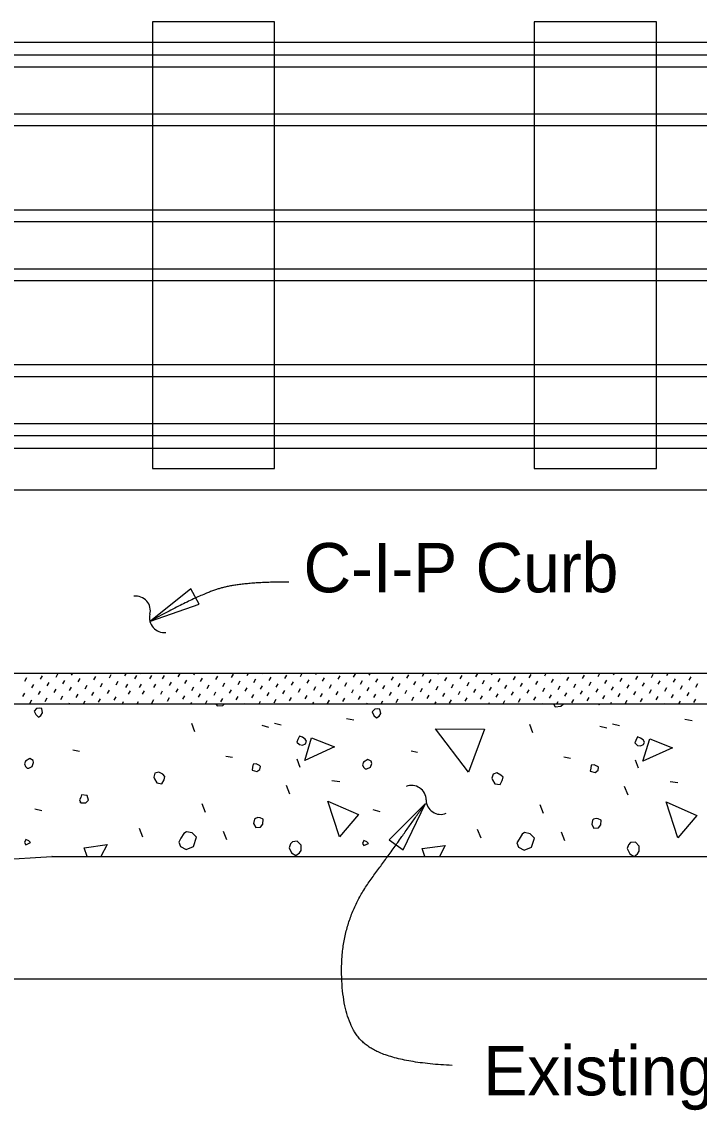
# Model space of a CAD drawing. Extents: x 1.5 to 68.7, y 0 to 31.1.
# Drawn here: x 31.375 to 34.147, y 9.197 to 13.648 of the extents above; entities that cross this region are included whole.
import ezdxf

# ---------------------------------------------------------------- set-up
doc = ezdxf.new("R2010")
doc.units = 0
for name, color, linetype in [('AdhocPoint_dp', 7, 'Continuous'), ('Patterning', 7, 'Continuous'), ('PlotBorder_dp', 7, 'Continuous'), ('SheetBorder_dp', 7, 'Continuous')]:
    doc.layers.add(name, color=color, linetype=linetype)

msp = doc.modelspace()

# ---------------------------------------------------------------- linework, layer by layer
at = {"layer": 'AdhocPoint_dp'}
for points in [[(31.9014, 11.1976), (32.1009, 11.2667), (32.067, 11.3286)], [(33.0264, 10.4517), (32.8772, 10.3022), (32.9348, 10.2614)]]:
    msp.add_lwpolyline(points, close=True, dxfattribs=at)
for centre, start, end in [((31.8414, 11.2396), 345.7563, 97.4835), ((31.9569, 11.2103), 165.7563, 277.4835), ((32.9696, 10.4655), 0.5042, 112.2314), ((33.0889, 10.4666), 180.5042, 292.2314)]:
    msp.add_arc(centre, 0.0596, start, end, dxfattribs=at)
for points in [[(32.467, 11.357), (32.2731, 11.357), (32.0952, 11.3038), (31.9014, 11.1976)], [(33.1354, 9.3803), (32.866, 9.3932), (32.6865, 9.5471), (32.68, 9.9706), (32.9173, 10.2978), (33.0264, 10.4518)]]:
    msp.add_open_spline(points, degree=2, dxfattribs=at)
at = {"layer": 'Patterning'}
for p, q in [((28.9195, 13.5645), (37.6978, 13.5645)), ((29.5771, 13.5123), (37.6978, 13.5123)), ((29.5783, 13.4641), (37.6978, 13.4641)), ((29.5831, 13.2713), (37.6978, 13.2713)), ((29.5842, 13.2231), (37.6978, 13.2231)), ((29.5807, 12.8791), (37.6978, 12.8791)), ((29.5795, 12.8309), (37.6978, 12.8309)), ((29.5747, 12.6381), (37.6978, 12.6381)), ((29.5735, 12.5899), (37.6978, 12.5899)), ((29.5842, 12.246), (37.6978, 12.246)), ((29.5831, 12.1978), (37.6978, 12.1978)), ((29.5783, 12.0049), (37.6978, 12.0049)), ((29.5771, 11.9567), (37.6978, 11.9567)), ((28.9195, 11.9044), (37.6978, 11.9044)), ((31.3878, 10.952), (31.3959, 10.966)), ((31.4513, 10.9601), (31.4594, 10.9741)), ((31.5148, 10.9682), (31.5229, 10.9822)), ((31.5425, 10.9405), (31.5506, 10.9545)), ((31.5783, 10.9763), (31.583, 10.9845)), ((31.606, 10.9486), (31.6141, 10.9626)), ((31.6418, 10.9844), (31.6418, 10.9845)), ((31.6695, 10.9567), (31.6776, 10.9707)), ((31.733, 10.9648), (31.7411, 10.9788)), ((31.7607, 10.9371), (31.7688, 10.9511)), ((31.7964, 10.9729), (31.8032, 10.9845)), ((31.8376, 10.9614), (31.8457, 10.9754)), ((31.8599, 10.981), (31.862, 10.9845)), ((31.8986, 10.9614), (31.9067, 10.9754)), ((31.9511, 10.9614), (31.9592, 10.9754)), ((32.0146, 10.9695), (32.0227, 10.9835)), ((32.0423, 10.9418), (32.0504, 10.9558)), ((32.0781, 10.9776), (32.0821, 10.9845)), ((32.1058, 10.9499), (32.1139, 10.9639)), ((32.1693, 10.958), (32.1774, 10.972)), ((32.2328, 10.9661), (32.2409, 10.9801)), ((32.2605, 10.9384), (32.2686, 10.9524)), ((32.2963, 10.9742), (32.3022, 10.9845)), ((32.324, 10.9465), (32.3321, 10.9605)), ((32.3598, 10.9823), (32.361, 10.9845)), ((32.3875, 10.9546), (32.3956, 10.9686)), ((32.451, 10.9627), (32.4591, 10.9767)), ((32.4787, 10.935), (32.4868, 10.949)), ((32.5145, 10.9708), (32.5224, 10.9845)), ((32.5422, 10.9431), (32.5503, 10.9571)), ((32.578, 10.9789), (32.5812, 10.9845)), ((32.6056, 10.9512), (32.6137, 10.9652)), ((32.6691, 10.9593), (32.6772, 10.9733)), ((32.7326, 10.9674), (32.7407, 10.9814)), ((32.7603, 10.9397), (32.7684, 10.9537)), ((32.7961, 10.9755), (32.8013, 10.9845)), ((32.8238, 10.9479), (32.8319, 10.9618)), ((32.8596, 10.9836), (32.8601, 10.9845)), ((32.8873, 10.956), (32.8954, 10.9699)), ((32.9508, 10.9641), (32.9589, 10.978)), ((32.9785, 10.9364), (32.9866, 10.9504)), ((33.0143, 10.9722), (33.0214, 10.9845)), ((33.042, 10.9445), (33.0501, 10.9585)), ((33.0778, 10.9803), (33.0802, 10.9845)), ((33.1055, 10.9526), (33.1136, 10.9666)), ((33.169, 10.9607), (33.1771, 10.9747)), ((33.2325, 10.9688), (33.2406, 10.9828)), ((33.2602, 10.9411), (33.2683, 10.9551)), ((33.296, 10.9769), (33.3004, 10.9845)), ((33.3237, 10.9492), (33.3318, 10.9632)), ((33.3871, 10.9573), (33.3952, 10.9713)), ((33.4506, 10.9654), (33.4587, 10.9794)), ((33.4783, 10.9377), (33.4864, 10.9517)), ((33.5141, 10.9735), (33.5205, 10.9845)), ((33.5418, 10.9458), (33.5499, 10.9598)), ((33.5776, 10.9816), (33.5793, 10.9845)), ((33.6053, 10.9539), (33.6134, 10.9679)), ((33.6688, 10.962), (33.6769, 10.976)), ((33.7323, 10.9701), (33.7404, 10.9841)), ((33.76, 10.9424), (33.7681, 10.9564)), ((33.7958, 10.9782), (33.7994, 10.9845)), ((33.8235, 10.9505), (33.8316, 10.9645)), ((33.887, 10.9586), (33.8951, 10.9726)), ((33.9505, 10.9667), (33.9586, 10.9807)), ((33.9782, 10.939), (33.9863, 10.953)), ((34.014, 10.9748), (34.0196, 10.9845)), ((34.0417, 10.9471), (34.0498, 10.9611)), ((34.0775, 10.9829), (34.0784, 10.9845)), ((34.1052, 10.9552), (34.1133, 10.9692)), ((31.4155, 10.9243), (31.4236, 10.9383)), ((31.4432, 10.8966), (31.4513, 10.9106)), ((31.479, 10.9324), (31.4871, 10.9464)), ((31.5067, 10.9047), (31.5148, 10.9187)), ((31.5702, 10.9128), (31.5783, 10.9268)), ((31.6337, 10.9209), (31.6418, 10.9349)), ((31.6614, 10.8932), (31.6695, 10.9072)), ((31.6972, 10.929), (31.7053, 10.943)), ((31.7249, 10.9013), (31.733, 10.9153)), ((31.8002, 10.9256), (31.8083, 10.9396)), ((31.8109, 10.8979), (31.8191, 10.9119)), ((31.856, 10.9256), (31.8641, 10.9396)), ((31.8681, 10.8979), (31.8762, 10.9119)), ((31.9153, 10.9256), (31.9234, 10.9396)), ((31.943, 10.8979), (31.9511, 10.9119)), ((31.9788, 10.9337), (31.9869, 10.9477)), ((32.0065, 10.906), (32.0146, 10.92)), ((32.07, 10.9141), (32.0781, 10.9281)), ((32.1335, 10.9222), (32.1416, 10.9362)), ((32.1612, 10.8945), (32.1693, 10.9085)), ((32.197, 10.9303), (32.2051, 10.9443)), ((32.2247, 10.9026), (32.2328, 10.9166)), ((32.2882, 10.9107), (32.2963, 10.9247)), ((32.3517, 10.9188), (32.3598, 10.9328)), ((32.3794, 10.8911), (32.3875, 10.9051)), ((32.4152, 10.9269), (32.4233, 10.9409)), ((32.4429, 10.8992), (32.451, 10.9132)), ((32.5064, 10.9073), (32.5145, 10.9213)), ((32.5698, 10.9154), (32.578, 10.9294)), ((32.6333, 10.9235), (32.6414, 10.9375)), ((32.661, 10.8958), (32.6691, 10.9098)), ((32.6968, 10.9316), (32.7049, 10.9456)), ((32.7245, 10.904), (32.7326, 10.9179)), ((32.788, 10.9121), (32.7961, 10.926)), ((32.8515, 10.9202), (32.8596, 10.9342)), ((32.8792, 10.8925), (32.8873, 10.9065)), ((32.915, 10.9283), (32.9231, 10.9423)), ((32.9427, 10.9006), (32.9508, 10.9146)), ((33.0062, 10.9087), (33.0143, 10.9227)), ((33.0697, 10.9168), (33.0778, 10.9308)), ((33.1332, 10.9249), (33.1413, 10.9389)), ((33.1609, 10.8972), (33.169, 10.9112)), ((33.1967, 10.933), (33.2048, 10.947)), ((33.2244, 10.9053), (33.2325, 10.9193)), ((33.2879, 10.9134), (33.296, 10.9274)), ((33.3513, 10.9215), (33.3595, 10.9355)), ((33.379, 10.8938), (33.3871, 10.9078)), ((33.4148, 10.9296), (33.4229, 10.9436)), ((33.4425, 10.9019), (33.4506, 10.9159)), ((33.506, 10.91), (33.5141, 10.924)), ((33.5695, 10.9181), (33.5776, 10.9321)), ((33.5972, 10.8904), (33.6053, 10.9044)), ((33.633, 10.9262), (33.6411, 10.9402)), ((33.6607, 10.8985), (33.6688, 10.9125)), ((33.6965, 10.9343), (33.7046, 10.9483)), ((33.7242, 10.9066), (33.7323, 10.9206)), ((33.7877, 10.9147), (33.7958, 10.9287)), ((33.8512, 10.9228), (33.8593, 10.9368)), ((33.8789, 10.8951), (33.887, 10.9091)), ((33.9147, 10.9309), (33.9228, 10.9449)), ((33.9424, 10.9032), (33.9505, 10.9172)), ((34.0059, 10.9113), (34.014, 10.9253)), ((34.0694, 10.9194), (34.0775, 10.9334)), ((34.0971, 10.8917), (34.1052, 10.9057)), ((34.1328, 10.9275), (34.141, 10.9415)), ((31.3797, 10.8885), (31.3878, 10.9025)), ((31.4074, 10.8608), (31.4155, 10.8748)), ((31.4709, 10.8689), (31.479, 10.8829)), ((31.5344, 10.877), (31.5425, 10.891)), ((31.568, 10.8595), (31.5702, 10.8633)), ((31.5979, 10.8851), (31.606, 10.8991)), ((31.6268, 10.8595), (31.6337, 10.8714)), ((31.6891, 10.8655), (31.6972, 10.8795)), ((31.7526, 10.8736), (31.7607, 10.8876)), ((31.7865, 10.8595), (31.7914, 10.868)), ((31.7881, 10.8595), (31.7883, 10.8599)), ((31.8469, 10.8595), (31.8518, 10.868)), ((31.9072, 10.8621), (31.9153, 10.8761)), ((31.9707, 10.8702), (31.9788, 10.8842)), ((32.0342, 10.8783), (32.0423, 10.8923)), ((32.067, 10.8595), (32.07, 10.8646)), ((32.0977, 10.8864), (32.1058, 10.9004)), ((32.1258, 10.8595), (32.1335, 10.8727)), ((32.1889, 10.8668), (32.197, 10.8808)), ((32.2524, 10.8749), (32.2605, 10.8889)), ((32.2872, 10.8595), (32.2882, 10.8612)), ((32.3159, 10.883), (32.324, 10.897)), ((32.346, 10.8595), (32.3517, 10.8693)), ((32.4071, 10.8634), (32.4152, 10.8774)), ((32.4706, 10.8715), (32.4787, 10.8855)), ((32.5341, 10.8796), (32.5422, 10.8936)), ((32.5661, 10.8595), (32.5698, 10.8659)), ((32.5975, 10.8877), (32.6056, 10.9017)), ((32.6252, 10.8601), (32.6333, 10.874)), ((32.6887, 10.8682), (32.6968, 10.8821)), ((32.7522, 10.8763), (32.7603, 10.8903)), ((32.7862, 10.8595), (32.788, 10.8626)), ((32.8157, 10.8844), (32.8238, 10.8984)), ((32.845, 10.8595), (32.8515, 10.8707)), ((32.9069, 10.8648), (32.915, 10.8788)), ((32.9704, 10.8729), (32.9785, 10.8869)), ((33.0339, 10.881), (33.042, 10.895)), ((33.0652, 10.8595), (33.0697, 10.8673)), ((33.0974, 10.8891), (33.1055, 10.9031)), ((33.1251, 10.8614), (33.1332, 10.8754)), ((33.1886, 10.8695), (33.1967, 10.8835)), ((33.2521, 10.8776), (33.2602, 10.8916)), ((33.2853, 10.8595), (33.2879, 10.8639)), ((33.3156, 10.8857), (33.3237, 10.8997)), ((33.3441, 10.8595), (33.3513, 10.872)), ((33.4067, 10.8661), (33.4148, 10.8801)), ((33.4702, 10.8742), (33.4783, 10.8882)), ((33.5054, 10.8595), (33.506, 10.8605)), ((33.5337, 10.8823), (33.5418, 10.8963)), ((33.5642, 10.8595), (33.5695, 10.8686)), ((33.6249, 10.8627), (33.633, 10.8767)), ((33.6884, 10.8708), (33.6965, 10.8848)), ((33.7519, 10.8789), (33.76, 10.8929)), ((33.7844, 10.8595), (33.7877, 10.8652)), ((33.8154, 10.887), (33.8235, 10.901)), ((33.8432, 10.8595), (33.8512, 10.8733)), ((33.9066, 10.8674), (33.9147, 10.8814)), ((33.9701, 10.8755), (33.9782, 10.8895)), ((34.0045, 10.8595), (34.0059, 10.8618)), ((34.0336, 10.8836), (34.0417, 10.8976)), ((34.0633, 10.8595), (34.0694, 10.8699)), ((34.1247, 10.864), (34.1328, 10.878)), ((32.0825, 10.7446), (32.0701, 10.7782)), ((32.3565, 10.7711), (32.3848, 10.764)), ((32.4082, 10.7804), (32.4365, 10.7733)), ((32.7038, 10.7994), (32.7339, 10.7941)), ((33.4657, 10.741), (33.4534, 10.7746)), ((33.7915, 10.7768), (33.8197, 10.7698)), ((34.0871, 10.7958), (34.1172, 10.7905)), ((33.7397, 10.7676), (33.768, 10.7605)), ((31.584, 10.6703), (31.6105, 10.665)), ((32.2097, 10.6456), (32.2363, 10.6403)), ((32.9672, 10.6668), (32.9937, 10.6615)), ((33.593, 10.6421), (33.6195, 10.6368)), ((32.5142, 10.5992), (32.5019, 10.6328)), ((33.8975, 10.5957), (33.8851, 10.6292)), ((32.4718, 10.4896), (32.4577, 10.5249)), ((32.6437, 10.5448), (32.6755, 10.5413)), ((33.8551, 10.486), (33.8409, 10.5214)), ((34.027, 10.5413), (34.0588, 10.5378)), ((31.4284, 10.4299), (31.4567, 10.4229)), ((32.1267, 10.414), (32.1125, 10.4494)), ((32.8117, 10.4264), (32.84, 10.4193)), ((33.5099, 10.4105), (33.4958, 10.4458)), ((31.8703, 10.3132), (31.8562, 10.3486)), ((32.2137, 10.3022), (32.1996, 10.3376)), ((33.2536, 10.3097), (33.2395, 10.3451)), ((33.597, 10.2987), (33.5829, 10.334))]:
    msp.add_line(p, q, dxfattribs=at)
for points in [[(31.9092, 11.8211), (32.4092, 11.8211), (32.4092, 13.6478), (31.9092, 13.6478)], [(33.4717, 11.8211), (33.9717, 11.8211), (33.9717, 13.6478), (33.4717, 13.6478)]]:
    msp.add_lwpolyline(points, close=True, dxfattribs=at)
for points in [[(32.169, 10.8594), (32.1744, 10.8507), (32.1974, 10.8524), (32.2044, 10.8594)], [(33.5501, 10.8594), (33.5577, 10.8471), (33.5806, 10.8489), (33.5895, 10.8577), (33.5912, 10.8594)], [(33.7367, 10.8529), (33.7345, 10.8594)], [(33.74, 10.8594), (33.7367, 10.8529)], [(31.4319, 10.8153), (31.4425, 10.8047), (31.4531, 10.8118), (31.4602, 10.8224), (31.4567, 10.84), (31.4478, 10.8418), (31.4355, 10.84), (31.4249, 10.8294), (31.4319, 10.8153)], [(32.8152, 10.8118), (32.8258, 10.8012), (32.8364, 10.8082), (32.8435, 10.8188), (32.84, 10.8365), (32.8311, 10.8383), (32.8187, 10.8365), (32.8081, 10.8259), (32.8152, 10.8118)], [(32.5107, 10.692), (32.5231, 10.6902), (32.5355, 10.6955), (32.539, 10.7061), (32.5337, 10.715), (32.5231, 10.722), (32.5107, 10.7273), (32.5036, 10.7132), (32.5001, 10.7026), (32.5107, 10.692)], [(33.2023, 10.5802), (33.068, 10.757), (33.2678, 10.7552), (33.2023, 10.5802)], [(32.5324, 10.6279), (32.5606, 10.7198), (32.6543, 10.6827), (32.5324, 10.6279)], [(33.894, 10.6885), (33.9064, 10.6867), (33.9187, 10.692), (33.9223, 10.7026), (33.917, 10.7114), (33.9064, 10.7185), (33.894, 10.7238), (33.8869, 10.7097), (33.8834, 10.6991), (33.894, 10.6885)], [(33.9156, 10.6244), (33.9439, 10.7163), (34.0376, 10.6792), (33.9156, 10.6244)], [(31.3966, 10.5961), (31.4036, 10.5961), (31.4178, 10.6032), (31.4231, 10.6191), (31.4213, 10.6279), (31.4072, 10.635), (31.3895, 10.6244), (31.386, 10.6138), (31.3895, 10.6032), (31.3966, 10.5961)], [(32.3176, 10.5873), (32.337, 10.582), (32.3494, 10.5908), (32.3512, 10.6032), (32.3476, 10.6067), (32.3335, 10.6138), (32.3211, 10.612), (32.3193, 10.5996), (32.3176, 10.5873)], [(32.7798, 10.5926), (32.7869, 10.5926), (32.8011, 10.5996), (32.8064, 10.6155), (32.8046, 10.6244), (32.7905, 10.6314), (32.7728, 10.6208), (32.7692, 10.6102), (32.7728, 10.5996), (32.7798, 10.5926)], [(33.7009, 10.5837), (33.7203, 10.5784), (33.7327, 10.5873), (33.7344, 10.5996), (33.7309, 10.6032), (33.7168, 10.6102), (33.7044, 10.6085), (33.7026, 10.5961), (33.7009, 10.5837)], [(31.9181, 10.5519), (31.9269, 10.536), (31.9481, 10.5325), (31.957, 10.5484), (31.9605, 10.5625), (31.9516, 10.5713), (31.9357, 10.5802), (31.9198, 10.5749), (31.9145, 10.559), (31.9181, 10.5519)], [(33.3013, 10.5484), (33.3102, 10.5325), (33.3314, 10.5289), (33.3402, 10.5448), (33.3438, 10.559), (33.3349, 10.5678), (33.319, 10.5766), (33.3031, 10.5713), (33.2978, 10.5554), (33.3013, 10.5484)], [(31.6158, 10.4547), (31.637, 10.4547), (31.6476, 10.4653), (31.6423, 10.4847), (31.6193, 10.4865), (31.6158, 10.4759), (31.6105, 10.467), (31.6158, 10.4547), (31.6122, 10.4582)], [(32.6751, 10.3146), (32.6274, 10.4613), (32.7529, 10.4065), (32.6751, 10.3146)], [(34.0584, 10.311), (34.0107, 10.4578), (34.1362, 10.403), (34.0584, 10.311)], [(32.3233, 10.3694), (32.3322, 10.3535), (32.3516, 10.3552), (32.3604, 10.3676), (32.3622, 10.3871), (32.3498, 10.3924), (32.341, 10.3941), (32.3304, 10.3906), (32.3269, 10.3871), (32.3233, 10.3694)], [(33.7066, 10.3658), (33.7154, 10.3499), (33.7349, 10.3517), (33.7437, 10.3641), (33.7455, 10.3835), (33.7331, 10.3888), (33.7243, 10.3906), (33.7137, 10.3871), (33.7101, 10.3835), (33.7066, 10.3658)], [(32.0241, 10.2761), (32.0471, 10.2638), (32.0772, 10.2761), (32.0895, 10.3132), (32.0719, 10.3309), (32.0489, 10.3362), (32.0383, 10.3292), (32.0259, 10.3097), (32.0171, 10.2938), (32.0241, 10.2761)], [(33.4074, 10.2726), (33.4304, 10.2602), (33.4604, 10.2726), (33.4728, 10.3097), (33.4551, 10.3274), (33.4322, 10.3327), (33.4215, 10.3256), (33.4092, 10.3062), (33.4003, 10.2903), (33.4074, 10.2726)], [(31.3908, 10.2828), (31.4103, 10.2916), (31.4032, 10.2987), (31.3908, 10.304), (31.3855, 10.2916), (31.3908, 10.2828)], [(31.6416, 10.2344), (31.6299, 10.2708), (31.7236, 10.2832), (31.6985, 10.2344)], [(32.4683, 10.2704), (32.4789, 10.2492), (32.4966, 10.2386), (32.5107, 10.2492), (32.5178, 10.2598), (32.5178, 10.281), (32.5019, 10.2969), (32.4824, 10.2951), (32.4736, 10.2863), (32.4683, 10.2704)], [(32.7741, 10.2792), (32.7935, 10.2881), (32.7865, 10.2951), (32.7741, 10.3004), (32.7688, 10.2881), (32.7741, 10.2792)], [(33.8516, 10.2668), (33.8622, 10.2456), (33.8798, 10.235), (33.894, 10.2456), (33.9011, 10.2562), (33.9011, 10.2775), (33.8851, 10.2934), (33.8657, 10.2916), (33.8569, 10.2828), (33.8516, 10.2668)], [(33.0238, 10.2344), (33.0132, 10.2673), (33.1069, 10.2797), (33.0836, 10.2344)], [(31.4997, 10.2344), (31.4987, 10.235), (31.4972, 10.2344)]]:
    msp.add_lwpolyline(points, dxfattribs=at)
at = {"layer": 'PlotBorder_dp'}
for p, q in [((26.2771, 11.7345), (36.6763, 11.7345)), ((27.4971, 10.9845), (37.6978, 10.9845)), ((28.2772, 10.8595), (34.2217, 10.8595)), ((27.4971, 9.9844), (31.4971, 10.2344)), ((31.4971, 10.2345), (37.6978, 10.2345)), ((27.4971, 9.7345), (36.6763, 9.7345))]:
    msp.add_line(p, q, dxfattribs=at)

# ---------------------------------------------------------------- texts
at = {"layer": 'SheetBorder_dp'}
for s, p in [('C-I-P Curb', (32.5274, 11.3149)), ('Existing Approach Slab', (33.2635, 9.2581))]:
    msp.add_text(s, height=0.2016, dxfattribs=at).set_placement(p)

doc.saveas('drawing.dxf')
